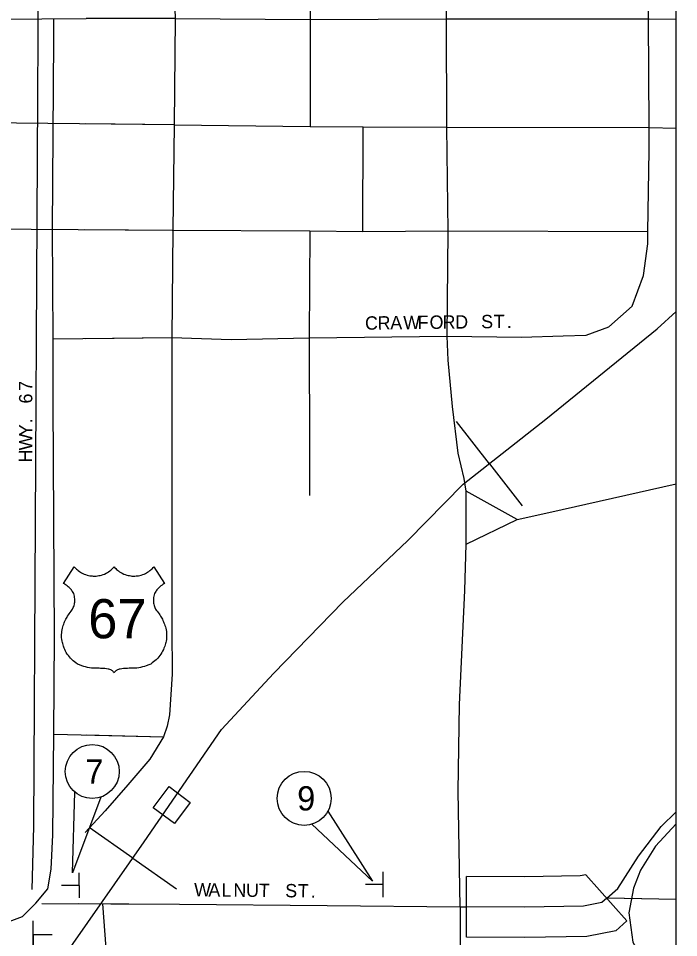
# Model space of a CAD drawing. Extents: x 988392 to 996681, y 1838707 to 1844440.
# Drawn here: x 993499 to 995131, y 1840620 to 1842892 of the extents above; entities that cross this region are included whole.
import ezdxf

# ---------------------------------------------------------------- set-up
doc = ezdxf.new("R2010")
doc.units = 0
for name, color, linetype in [('G-Border-Sheet', 7, 'Continuous'), ('Level 22', 7, 'Continuous'), ('Level 3', 7, 'Continuous'), ('Level 31', 7, 'Continuous'), ('Level 33', 7, 'Continuous'), ('Level 35', 7, 'Continuous'), ('Level 40', 7, 'Continuous'), ('Level 49', 7, 'Continuous'), ('Level 6', 7, 'Continuous'), ('Level 8', 7, 'Continuous'), ('R_Draft', 7, 'Continuous')]:
    doc.layers.add(name, color=color, linetype=linetype)

msp = doc.modelspace()

# ---------------------------------------------------------------- linework, layer by layer
at = {"layer": 'G-Border-Sheet'}
msp.add_lwpolyline([(995124.8, 1844439.6), (989844.9, 1844439.6), (989844.9, 1838706.8), (995124.8, 1838706.8)], close=True, dxfattribs=at)
at = {"layer": 'Level 3'}
for p, q in [((993648.2, 1840780), (993648.6, 1840718.1)), ((994399.5, 1840782.3), (994399.7, 1840720.4)), ((993647.5, 1840749.2), (993605.3, 1840748.9)), ((994398.7, 1840751.5), (994356.5, 1840751.4)), ((993535.6, 1840594.2), (993535.2, 1840661.7)), ((993535.7, 1840597), (993535.3, 1840658.8)), ((993536.4, 1840627.8), (993582.5, 1840628.1)), ((993536.4, 1840627.8), (993578.6, 1840628))]:
    msp.add_line(p, q, dxfattribs=at)
at = {"layer": 'Level 31'}
msp.add_line((994901.9, 1840775.3), (995003, 1840661.3), dxfattribs=at)
for points in [[(994129.9, 1841273.7), (994300.5, 1841449), (994461.9, 1841601.6), (994598.4, 1841740.5), (994803.1, 1841901), (995078.4, 1842124.1), (995124.8, 1842167.1)], [(994129.9, 1841273.7), (994300.5, 1841449), (994461.9, 1841601.6), (994598.4, 1841740.5), (994803.1, 1841901), (995078.4, 1842124.1), (995124.8, 1842167.1)], [(993296, 1840169.9), (993414.4, 1840315.7), (993597.7, 1840553.9), (993810, 1840856.5), (994001.1, 1841134.2), (994129.9, 1841273.7)], [(993296, 1840169.9), (993414.4, 1840315.7), (993597.7, 1840553.9), (993810, 1840856.5), (994001.1, 1841134.2), (994129.9, 1841273.7)], [(994606.5, 1840620.9), (994607, 1840770.9)], [(994901.9, 1840775.3), (994888, 1840772.6), (994749.7, 1840770.4), (994607, 1840770.9)], [(994953.2, 1840717.4), (994941.2, 1840706.7), (994896, 1840697.7), (994750.1, 1840695.4), (994606.8, 1840695.9)], [(995003, 1840661.3), (994975.8, 1840637.2), (994904, 1840622.8), (994750.6, 1840620.4), (994606.5, 1840620.9)]]:
    msp.add_lwpolyline(points, dxfattribs=at)
at = {"layer": 'Level 33'}
msp.add_line((991774, 1842877), (993666.6, 1842891.5), dxfattribs=at)
for points in [[(993885.4, 1843434.5), (993885.9, 1843164.2), (993884.8, 1842939.4), (993885.9, 1842891.3), (993883.7, 1842628.9), (993880.3, 1842369.2), (993878, 1842103.4), (993878, 1841871.4), (993878, 1841621.4), (993878, 1841384.9), (993879.2, 1841271.4), (993872.4, 1841170.7), (993866.7, 1841142.4), (993857.7, 1841116.4), (993823.8, 1841061), (993769.5, 1840997.6), (993713, 1840933.1), (993663.9, 1840879.5)], [(993885.7, 1843264.5), (993885.9, 1843164.2), (993884.8, 1842939.4), (993885.9, 1842891.3), (993883.7, 1842628.9), (993880.3, 1842369.2), (993878, 1842103.4), (993878, 1841871.4), (993878, 1841621.4), (993878, 1841384.9), (993879.2, 1841271.4), (993872.4, 1841170.7), (993866.7, 1841142.4), (993857.7, 1841116.4), (993823.8, 1841061), (993769.5, 1840997.6), (993713, 1840933.1), (993663.9, 1840879.5)], [(994559.2, 1842106.7), (994561.6, 1842366), (994558.2, 1842622.8), (994557, 1842889.1), (994558.4, 1843151.3)], [(994559.2, 1842106.7), (994561.6, 1842366), (994558.2, 1842622.8), (994557, 1842889.1), (994558.4, 1843151.3)], [(994559.2, 1842106.7), (994742.7, 1842103.5), (994845.6, 1842106.9), (994902.1, 1842109.2), (994958.6, 1842129.5), (995016.3, 1842180.4), (995044.5, 1842256.3), (995054.7, 1842334.3), (995054.7, 1842363.8), (995058.1, 1842565.2), (995058.1, 1842622.2), (995056.9, 1842890.4), (995056.7, 1843160.1)], [(994559.2, 1842106.7), (994742.7, 1842103.5), (994845.6, 1842106.9), (994902.1, 1842109.2), (994958.6, 1842129.5), (995016.3, 1842180.4), (995044.5, 1842256.3), (995054.7, 1842334.3), (995054.7, 1842363.8), (995058.1, 1842565.2), (995058.1, 1842622.2), (995056.9, 1842890.4), (995056.7, 1843160.1)], [(994217, 1843148.7), (994220.4, 1842888.5), (994220.4, 1842624.5)], [(994217, 1843148.7), (994220.4, 1842888.5), (994220.4, 1842624.5)], [(993885.9, 1842891.3), (993666.6, 1842891.5)], [(993885.9, 1842891.3), (993666.6, 1842891.5)], [(993885.9, 1842891.3), (994220.4, 1842888.5), (994556.5, 1842890.5), (995058.1, 1842890.4), (995124.8, 1842890)], [(993885.9, 1842891.3), (994220.4, 1842888.5), (994556.5, 1842890.5), (995058.1, 1842890.4), (995124.8, 1842890)], [(993883.7, 1842628.9), (993415.1, 1842633.9)], [(993883.7, 1842628.9), (993665.1, 1842631.2)], [(993883.7, 1842628.9), (994220.4, 1842624.5), (994351.5, 1842623.8)], [(993883.7, 1842628.9), (994220.4, 1842624.5), (994351.5, 1842623.8)], [(994350.4, 1842364.3), (994351.5, 1842623.8)], [(994350.4, 1842364.3), (994351.5, 1842623.8)], [(994351.5, 1842623.8), (994558.2, 1842622.8), (995058.1, 1842622.2), (995124.8, 1842620.3)], [(994351.5, 1842623.8), (994558.2, 1842622.8), (995058.1, 1842622.2), (995124.8, 1842620.3)], [(993879.2, 1842367.1), (993413.2, 1842371.1)], [(993879.2, 1842367.1), (993663.2, 1842368.9)], [(994350.4, 1842364.3), (994219.3, 1842365.5), (993879.2, 1842367.1)], [(994350.4, 1842364.3), (994219.3, 1842365.5), (993879.2, 1842367.1)], [(994219.3, 1842365.5), (994217.5, 1842102.5)], [(994219.3, 1842365.5), (994217.5, 1842102.5)], [(995054.7, 1842363.8), (994561.6, 1842366), (994350.4, 1842364.3)], [(995054.7, 1842363.8), (994561.6, 1842366), (994350.4, 1842364.3)], [(993584.4, 1842099.9), (993878, 1842103.4), (994024.4, 1842098.2), (994217.5, 1842102.5), (994559.2, 1842106.7)], [(993664.4, 1842100.8), (993878, 1842103.4), (994024.4, 1842098.2), (994217.5, 1842102.5), (994559.2, 1842106.7)], [(994590.8, 1840695.9), (994586.3, 1840982.1), (994589.2, 1841195.8), (994602.1, 1841478.2), (994605.5, 1841592.4), (994605.5, 1841723.6), (994601, 1841754.9), (994586.3, 1841817.1), (994571.6, 1841932.5), (994561.5, 1842046.7), (994559.2, 1842106.7)], [(994217.5, 1842102.5), (994218.8, 1841824.4), (994218.8, 1841713)], [(994217.5, 1842102.5), (994218.8, 1841824.4), (994218.8, 1841713)], [(994605.5, 1841592.4), (994731.8, 1841653.1), (994810.3, 1841670.6), (995124.8, 1841741.5)], [(994731.8, 1841653.1), (994605.5, 1841723.6)], [(993586.6, 1841122.7), (993857.7, 1841116.4)], [(993666.2, 1841120.8), (993857.7, 1841116.4)], [(994953.2, 1840717.4), (994980.8, 1840741.8), (995031.6, 1840821), (995088.2, 1840894.4), (995124.8, 1840931.2)], [(993556.8, 1840704.5), (993897.2, 1840702.9), (994262.3, 1840699.5), (994590.8, 1840695.9)], [(993597.2, 1840282.6), (993576.2, 1840316.9), (993571.8, 1840342.7), (993578.5, 1840366.3), (993623.3, 1840421.2), (993683.8, 1840485.1), (993708.4, 1840519.9), (993718.5, 1840561.4), (993707.2, 1840703.8)], [(993646.9, 1840704), (993897.2, 1840702.9), (994262.3, 1840699.5), (994590.8, 1840695.9)], [(994590.8, 1840695.9), (994591.8, 1840389.2), (994590.7, 1840207.6), (994592, 1840058.3)], [(994590.8, 1840695.9), (994606.8, 1840695.9)], [(994606.8, 1840695.9), (994606.9, 1840695.9)]]:
    msp.add_lwpolyline(points, dxfattribs=at)
at = {"layer": 'Level 35'}
for points in [[(995074, 1840846.3), (995124.8, 1840901.4)], [(995074, 1840846.3), (995036.8, 1840786.5), (995019.5, 1840742.6), (995007.6, 1840681.5), (995018.2, 1840608.4), (995063.3, 1840528.6), (995109.8, 1840470.1), (995131.1, 1840430.3), (995121.8, 1840373.1), (995124.8, 1840360.1)]]:
    msp.add_lwpolyline(points, dxfattribs=at)
at = {"layer": 'Level 40'}
for p, q in [((994663.2, 1841791.2), (994581.8, 1841895.1)), ((994663.2, 1841791.2), (994744.6, 1841687.4)), ((993781.7, 1840816.2), (993673.7, 1840892)), ((993781.7, 1840816.2), (993889.8, 1840740.4))]:
    msp.add_line(p, q, dxfattribs=at)
msp.add_lwpolyline([(993597.7, 1840553.9), (993810, 1840856.5), (994001.1, 1841134.2), (994129.9, 1841273.7), (994300.5, 1841449), (994461.9, 1841601.6), (994598.4, 1841740.5), (994803.1, 1841901), (995078.4, 1842124.1), (995124.8, 1842167.1)], dxfattribs=at)
msp.add_lwpolyline([(993597.7, 1840553.9), (993810, 1840856.5), (994001.1, 1841134.2), (994129.9, 1841273.7), (994300.5, 1841449), (994461.9, 1841601.6), (994598.4, 1841740.5), (994803.1, 1841901), (995078.4, 1842124.1), (995124.8, 1842167.1)], dxfattribs=at)
msp.add_lwpolyline([(993923.5, 1840954), (993884.4, 1840901.7), (993832.1, 1840940.8), (993871.1, 1840993.1)], close=True, dxfattribs=at)
at = {"layer": 'Level 49'}
for points in [[(993637.5, 1841301.2), (993634.4, 1841303.8), (993631.3, 1841306.7), (993627.6, 1841310.5), (993624.8, 1841313.8), (993622.3, 1841317), (993619.7, 1841320.7), (993617.2, 1841324.7), (993615.3, 1841328.2), (993613.6, 1841331.8), (993612, 1841335.2), (993610.3, 1841340), (993609.1, 1841343.8), (993608.2, 1841347), (993607.5, 1841349.7), (993606.8, 1841352.9), (993606.1, 1841357), (993605.6, 1841361.4), (993605.5, 1841365.2), (993605.5, 1841369), (993605.7, 1841373), (993606.2, 1841376.8), (993606.7, 1841380.3), (993607.6, 1841384.4), (993608.6, 1841387.8), (993609.6, 1841391), (993610.9, 1841394.8), (993612.1, 1841397.9), (993613.1, 1841400.3), (993614.5, 1841403.6), (993616.1, 1841406.9), (993617.6, 1841409.8), (993618.9, 1841412.2), (993620.4, 1841414.7), (993622.2, 1841417.6), (993624.2, 1841420.5), (993626.3, 1841423.4), (993628.9, 1841426.8), (993631, 1841429.3), (993632.8, 1841432.1), (993634.5, 1841435.7), (993635.6, 1841438.5), (993636.4, 1841441), (993637.1, 1841443.9), (993637.6, 1841446.5), (993638, 1841449.3), (993638.2, 1841451.5), (993638.3, 1841454.4), (993638.2, 1841457.4), (993637.8, 1841460.5), (993637.3, 1841463.9), (993636.5, 1841467.1), (993635.4, 1841470.3), (993634.1, 1841472.8), (993632.6, 1841475.1), (993631.1, 1841477.2), (993629.6, 1841479.1), (993628.1, 1841480.9), (993626, 1841483.2), (993624, 1841485.3), (993622, 1841487.2), (993619.7, 1841489.1), (993616.9, 1841491.4), (993614.7, 1841492.9), (993612.5, 1841494.3), (993610.6, 1841495.5), (993637, 1841536.4), (993638.6, 1841534.5), (993640.6, 1841532.5), (993642.6, 1841530.6), (993644.5, 1841528.8), (993646.8, 1841527), (993649.5, 1841525), (993652.4, 1841523.1), (993655, 1841521.5), (993657.9, 1841520), (993661, 1841518.6), (993664.4, 1841517.3), (993668.4, 1841516), (993671.7, 1841515.1), (993675.3, 1841514.4), (993678.1, 1841514), (993680.9, 1841513.7), (993683.8, 1841513.5), (993687.2, 1841513.4), (993691.4, 1841513.6), (993694.4, 1841513.9), (993697.7, 1841514.5), (993700.8, 1841515.1), (993704.2, 1841516), (993707.9, 1841517.2), (993711.2, 1841518.5), (993715.5, 1841520.4), (993718.9, 1841522.3), (993721.8, 1841524.1), (993724.6, 1841526.1), (993726.9, 1841527.8), (993729.2, 1841529.9), (993731.4, 1841531.9), (993733.3, 1841533.9), (993735.3, 1841536.1)], [(993735.3, 1841536.1), (993737.4, 1841533.9), (993739.3, 1841531.9), (993741.5, 1841529.9), (993743.8, 1841527.8), (993746.1, 1841526.1), (993748.9, 1841524.1), (993751.8, 1841522.3), (993755.2, 1841520.4), (993759.5, 1841518.5), (993762.7, 1841517.2), (993766.5, 1841516), (993769.9, 1841515.1), (993773, 1841514.5), (993776.3, 1841513.9), (993779.3, 1841513.6), (993783.5, 1841513.4), (993786.9, 1841513.5), (993789.8, 1841513.7), (993792.6, 1841514), (993795.4, 1841514.4), (993799, 1841515.1), (993802.3, 1841516), (993806.3, 1841517.3), (993809.7, 1841518.6), (993812.8, 1841520), (993815.7, 1841521.5), (993818.3, 1841523.1), (993821.2, 1841525), (993823.9, 1841527), (993826.2, 1841528.8), (993828.1, 1841530.6), (993830.1, 1841532.5), (993832.1, 1841534.5), (993833.7, 1841536.4), (993860.1, 1841495.5), (993858.2, 1841494.3), (993856, 1841492.9), (993853.8, 1841491.4), (993851, 1841489.1), (993848.7, 1841487.2), (993846.7, 1841485.3), (993844.7, 1841483.2), (993842.6, 1841480.9), (993841.1, 1841479.1), (993839.6, 1841477.2), (993838.1, 1841475.1), (993836.6, 1841472.8), (993835.2, 1841470.3), (993834.2, 1841467.1), (993833.4, 1841463.9), (993832.9, 1841460.5), (993832.5, 1841457.4), (993832.4, 1841454.4), (993832.5, 1841451.5), (993832.7, 1841449.3), (993833.1, 1841446.5), (993833.6, 1841443.9), (993834.3, 1841441), (993835.1, 1841438.5), (993836.2, 1841435.7), (993837.9, 1841432.1), (993839.7, 1841429.3), (993841.8, 1841426.8), (993844.4, 1841423.4), (993846.5, 1841420.5), (993848.5, 1841417.6), (993850.3, 1841414.7), (993851.8, 1841412.2), (993853.1, 1841409.8), (993854.6, 1841406.9), (993856.2, 1841403.6), (993857.6, 1841400.3), (993858.6, 1841397.9), (993859.8, 1841394.8), (993861.1, 1841391), (993862.1, 1841387.8), (993863.1, 1841384.4), (993863.9, 1841380.3), (993864.5, 1841376.8), (993865, 1841373), (993865.2, 1841369), (993865.2, 1841365.2), (993865.1, 1841361.4), (993864.6, 1841357), (993863.9, 1841352.9), (993863.2, 1841349.7), (993862.5, 1841347), (993861.6, 1841343.8), (993860.4, 1841340), (993858.6, 1841335.2), (993857.1, 1841331.8), (993855.4, 1841328.2), (993853.5, 1841324.7), (993851, 1841320.7), (993848.4, 1841317), (993845.9, 1841313.8), (993843.1, 1841310.5), (993839.4, 1841306.7), (993836.3, 1841303.8), (993833.1, 1841301.2)], [(993735.3, 1841274), (993734.2, 1841275.9), (993732.9, 1841277.5), (993731.3, 1841279.1), (993729.7, 1841280.5), (993728.5, 1841281.3), (993727.1, 1841282), (993724.7, 1841283), (993722.7, 1841283.4), (993720.3, 1841283.7), (993716.3, 1841284.2), (993712.2, 1841284.7), (993708.9, 1841284.9), (993705.7, 1841285.2), (993702, 1841285.3), (993698, 1841285.5), (993694.1, 1841285.5), (993690, 1841285.5), (993685.3, 1841285.7), (993679.1, 1841286.2), (993674.2, 1841286.9), (993669.6, 1841287.7), (993664.8, 1841288.8), (993660.5, 1841290), (993655.7, 1841291.6), (993649.9, 1841293.8), (993644.8, 1841296.1), (993640.9, 1841298.7), (993637.5, 1841301.2)], [(993833.1, 1841301.2), (993829.8, 1841298.7), (993825.8, 1841296.1), (993820.8, 1841293.8), (993815, 1841291.6), (993810.2, 1841290), (993805.9, 1841288.8), (993801, 1841287.7), (993796.5, 1841286.9), (993791.6, 1841286.2), (993785.4, 1841285.7), (993780.7, 1841285.5), (993776.6, 1841285.5), (993772.7, 1841285.5), (993768.7, 1841285.3), (993765, 1841285.2), (993761.7, 1841284.9), (993758.5, 1841284.7), (993754.4, 1841284.2), (993750.4, 1841283.7), (993748, 1841283.4), (993746, 1841283), (993743.6, 1841282), (993742.2, 1841281.3), (993741, 1841280.5), (993739.4, 1841279.1), (993737.8, 1841277.5), (993736.5, 1841275.9), (993735.3, 1841274)]]:
    msp.add_lwpolyline(points, dxfattribs=at)
at = {"layer": 'Level 6'}
for points in [[(995124.8, 1840714.6), (994953.3, 1840717.4)], [(995124.8, 1840714.6), (994953.4, 1840717.4)], [(995124.8, 1840714.6), (994953.4, 1840717.4)], [(995124.8, 1840714.6), (994954.9, 1840717.4)]]:
    msp.add_lwpolyline(points, dxfattribs=at)
at = {"layer": 'Level 8'}
for points in [[(993702.4, 1840967.3), (993632.5, 1840779.8), (993638.5, 1840979.5)], [(994263.8, 1840932.4), (994373.8, 1840759.2), (994224.6, 1840900.4)]]:
    msp.add_lwpolyline(points, dxfattribs=at)
for centre in [(993681.3, 1841030.5), (994205.2, 1840964.2)]:
    msp.add_circle(centre, 66.7, dxfattribs=at)
at = {"layer": 'R_Draft'}
msp.add_line((993584.4, 1842099.5), (993583.2, 1842370.2), dxfattribs=at)
for points in [[(993548.8, 1843148.9), (993536, 1840894.4), (993531.9, 1840739.2)], [(993583.2, 1842369.7), (993586.6, 1842839.9), (993586.6, 1842891.6)], [(992879.3, 1840571.9), (992985.6, 1840610.6), (993056.1, 1840628.5), (993134.8, 1840638.9), (993177.2, 1840640.2), (993386.8, 1840641.5), (993456.2, 1840652.3), (993509, 1840672), (993542, 1840705.1), (993571.7, 1840740.8), (993579.5, 1840789.6), (993583.8, 1840873.8), (993586.2, 1841123.4), (993587.6, 1841363.1), (993584.3, 1841942.6), (993584.4, 1842099.3)]]:
    msp.add_lwpolyline(points, dxfattribs=at)

# ---------------------------------------------------------------- texts
at = {"layer": 'Level 22'}
msp.add_text('67', height=96.8, dxfattribs=at).set_placement((993671.4, 1841359.7))
at = {"layer": 'Level 8'}
for s, p in [('7', (993664.3, 1841000.5)), ('9', (994188, 1840934.2))]:
    msp.add_text(s, height=60, dxfattribs=at).set_placement(p)
at = {"layer": 'R_Draft'}
for s, rotation, p in [('C', 0.7068, (994355.9, 1842122.2)), ('R', 0.7068, (994387.1, 1842122.6)), ('A', 0.7068, (994418.3, 1842123)), ('W', 0.7068, (994450.5, 1842123.4)), ('F', 0.7068, (994485.8, 1842123.8)), ('O', 0.7068, (994515.5, 1842124.2)), ('R', 0.7068, (994547.7, 1842124.6)), ('D', 0.7068, (994578.9, 1842124.9)), ('S', 0.7068, (994643, 1842125.7)), ('T', 0.7068, (994674.2, 1842126.1)), ('.', 0.7068, (994706.4, 1842126.5)), ('7', 89.9353, (993533.2, 1841971.1)), ('6', 89.9353, (993533.2, 1841939.9)), ('Y', 89.9353, (993533.1, 1841859.1)), ('.', 89.9353, (993533.1, 1841890.8)), ('W', 89.5938, (993532.8, 1841823.8)), ('H', 89.5938, (993532.6, 1841794.2)), ('W', 359.4674, (993933, 1840722)), ('A', 359.4674, (993968.4, 1840721.6)), ('L', 359.4674, (994000.6, 1840721.3)), ('N', 359.4674, (994030.2, 1840721)), ('U', 359.4674, (994061.4, 1840720.8)), ('T', 359.3709, (994093.1, 1840720.4)), ('S', 359.3709, (994158.3, 1840719.7)), ('T', 359.3709, (994189.5, 1840719.4)), ('.', 359.3709, (994221.7, 1840719))]:
    msp.add_text(s, height=33, rotation=rotation, dxfattribs=at).set_placement(p)

doc.saveas('drawing.dxf')
